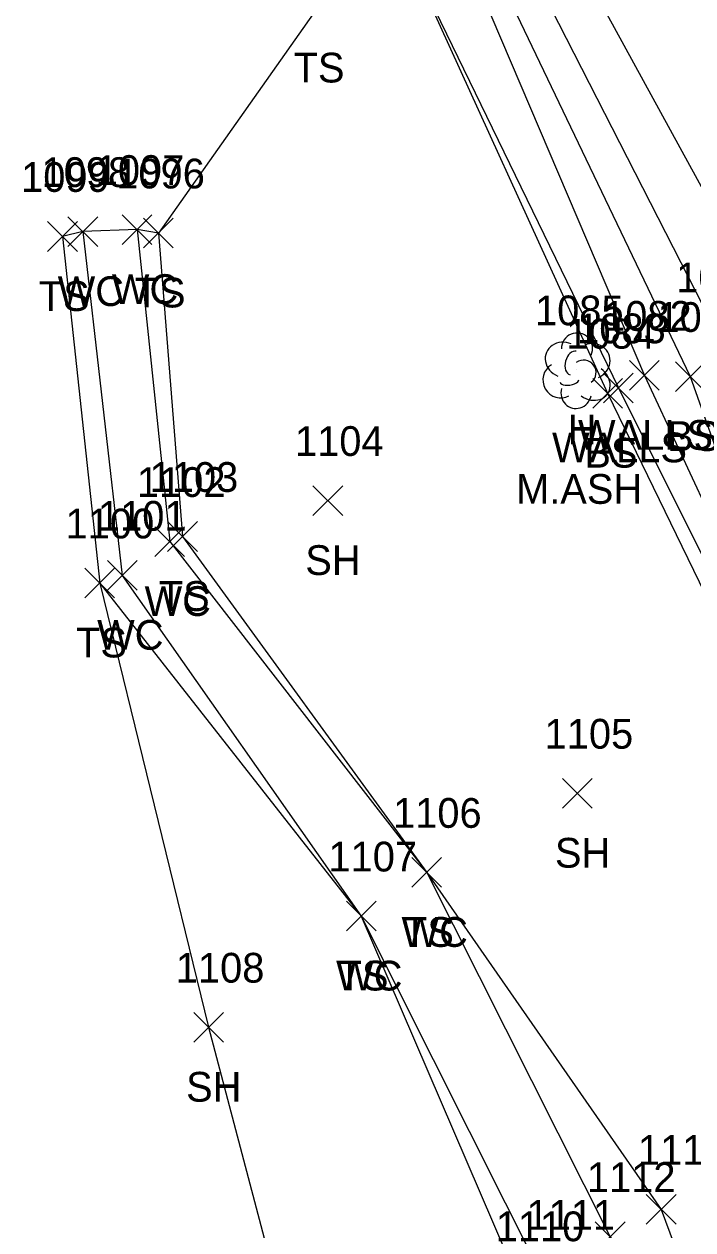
# Model space of a CAD drawing. Extents: x 1441651 to 1442140, y 243798 to 245625.
# Drawn here: x 1441903.8 to 1441948.7, y 245501.1 to 245582.1 of the extents above; entities that cross this region are included whole.
import ezdxf

# ---------------------------------------------------------------- set-up
doc = ezdxf.new("R2010")
doc.units = 0
for name, color, linetype in [('L_A', 7, 'Continuous'), ('L_C', 7, 'Continuous'), ('L_I', 7, 'Continuous'), ('L_TIC', 7, 'Continuous'), ('LAWE', 7, 'Continuous'), ('LELB', 7, 'Continuous'), ('LSOGP', 7, 'Continuous'), ('LTD', 7, 'Continuous'), ('LWS', 7, 'Continuous'), ('PEU', 7, 'Continuous')]:
    doc.layers.add(name, color=color, linetype=linetype)

msp = doc.modelspace()

# ---------------------------------------------------------------- linework, layer by layer
at = {"layer": 'L_TIC'}
for points in [[(1441905.336, 245566.87), (1441907.336, 245568.87)], [(1441907.336, 245566.87), (1441905.336, 245568.87)], [(1441906.704, 245567.198), (1441908.704, 245569.198)], [(1441908.704, 245567.198), (1441906.704, 245569.198)], [(1441910.342, 245567.336), (1441912.342, 245569.336)], [(1441912.342, 245567.336), (1441910.342, 245569.336)], [(1441911.774, 245567.104), (1441913.774, 245569.104)], [(1441913.774, 245567.104), (1441911.774, 245569.104)], [(1441944.41, 245557.535), (1441946.41, 245559.535)], [(1441946.41, 245557.535), (1441944.41, 245559.535)], [(1441947.491, 245557.459), (1441949.491, 245559.459)], [(1441949.491, 245557.459), (1441947.491, 245559.459)], [(1441941.939, 245556.338), (1441943.939, 245558.338)], [(1441943.939, 245556.338), (1441941.939, 245558.338)], [(1441942.666, 245556.696), (1441944.666, 245558.696)], [(1441944.666, 245556.696), (1441942.666, 245558.696)], [(1441923.153, 245549.123), (1441925.153, 245551.123)], [(1441925.153, 245549.123), (1441923.153, 245551.123)], [(1441912.54, 245546.368), (1441914.54, 245548.368)], [(1441914.54, 245546.368), (1441912.54, 245548.368)], [(1441913.394, 245546.708), (1441915.394, 245548.708)], [(1441915.394, 245546.708), (1441913.394, 245548.708)], [(1441909.354, 245544.097), (1441911.354, 245546.097)], [(1441911.354, 245544.097), (1441909.354, 245546.097)], [(1441907.838, 245543.581), (1441909.838, 245545.581)], [(1441909.838, 245543.581), (1441907.838, 245545.581)], [(1441939.916, 245529.451), (1441941.916, 245531.451)], [(1441941.916, 245529.451), (1441939.916, 245531.451)], [(1441929.794, 245524.129), (1441931.794, 245526.129)], [(1441931.794, 245524.129), (1441929.794, 245526.129)], [(1441929.794, 245524.129), (1441931.794, 245526.129)], [(1441931.794, 245524.129), (1441929.794, 245526.129)], [(1441925.401, 245521.195), (1441927.401, 245523.195)], [(1441927.401, 245521.195), (1441925.401, 245523.195)], [(1441925.401, 245521.195), (1441927.401, 245523.195)], [(1441927.401, 245521.195), (1441925.401, 245523.195)], [(1441915.149, 245513.724), (1441917.149, 245515.724)], [(1441917.149, 245513.724), (1441915.149, 245515.724)], [(1441945.539, 245501.48), (1441947.539, 245503.48)], [(1441947.539, 245501.48), (1441945.539, 245503.48)], [(1441942.112, 245499.641), (1441944.112, 245501.641)], [(1441944.112, 245499.641), (1441942.112, 245501.641)]]:
    msp.add_lwpolyline(points, dxfattribs=at)
at = {"layer": 'LAWE'}
for points in [[(1441907.704, 245568.198), (1441910.354, 245545.097), (1441926.401, 245522.195), (1441938.487, 245498.109), (1441943.431, 245489.962), (1441943.382, 245477.871), (1441945.819, 245463.28), (1441949.518, 245451.716), (1441958.04, 245451.396), (1441967.21, 245432.067), (1441993.811, 245408.343), (1442003.996, 245402.527), (1442022.028, 245379.959)], [(1441911.342, 245568.336), (1441913.54, 245547.368), (1441930.794, 245525.129), (1441943.112, 245500.641), (1441948.928, 245491.303), (1441946.177, 245479.068), (1441949.055, 245463.199), (1441952.693, 245455.284), (1441960.253, 245454.331), (1441970.926, 245435.223), (1441995.301, 245411.435), (1442005.916, 245405.86), (1442024.361, 245389.769), (1442032.995, 245390.022)]]:
    msp.add_lwpolyline(points, dxfattribs=at)
at = {"layer": 'LELB'}
for points in [[(1441935.553, 245590.253), (1441950.412, 245561.12), (1441965.846, 245535.511), (1441982.294, 245505.635), (1441993.222, 245488.677)], [(1441933.718, 245589.334), (1441948.491, 245558.459), (1441956.206, 245536.697), (1441975.054, 245500.102), (1441979.331, 245493.092), (1441987.533, 245478.538), (1441986.565, 245474.385), (1441981.273, 245469.984), (1441969.099, 245476.162)], [(1441929.024, 245587.875), (1441942.939, 245557.338), (1441953.315, 245535.956), (1441954.957, 245536.46), (1441956.206, 245536.697)], [(1441923.447, 245583.224), (1441912.774, 245568.104), (1441914.394, 245547.708), (1441930.794, 245525.129), (1441946.539, 245502.48), (1441950.678, 245491.319), (1441947.348, 245479.457), (1441950.826, 245463.211), (1441954.445, 245457.195), (1441962.212, 245455.423), (1441972.577, 245437.756), (1441995.951, 245413.456), (1442007.462, 245408.084), (1442021.352, 245397.079), (1442029.302, 245403.168), (1442035.632, 245410.326), (1442039.926, 245412.912), (1442042.785, 245414.272)], [(1441906.336, 245567.87), (1441908.838, 245544.581), (1441926.401, 245522.195), (1441937.072, 245497.343), (1441939.983, 245490.583), (1441942.033, 245477.517), (1441944.373, 245463.316), (1441948.224, 245450.684), (1441957.161, 245448.976), (1441965.891, 245430.984), (1441993.118, 245407.16), (1442003.121, 245400.589), (1442010.091, 245391.874)]]:
    msp.add_lwpolyline(points, dxfattribs=at)
at = {"layer": 'LSOGP'}
msp.add_lwpolyline([(1441923.447, 245583.224), (1441912.774, 245568.104), (1441911.342, 245568.336), (1441907.704, 245568.198), (1441906.336, 245567.87), (1441908.838, 245544.581), (1441916.149, 245514.724), (1441923.283, 245487.648)], dxfattribs=at)
at = {"layer": 'LTD'}
msp.add_line((1441940.839, 245558.905), (1441940.839, 245558.905), dxfattribs=at)
msp.add_line((1441940.839, 245558.905), (1441940.839, 245558.905), dxfattribs=at)
msp.add_arc((1441940.886, 245560.339), 1.047, 335.52715, 180.95627, dxfattribs=at)
for centre, major_axis, ratio, start_param, end_param in [((1441940.047, 245559.572), (1.21, -0.512), 0.895232, 1.570796, 4.712389), ((1441941.881, 245559.489), (-1.141, -0.483), 0.949671, 1.570796, 4.712389), ((1441940.631, 245559.364), (-0.208, -0.792), 0.645439, 3.141593, 6.283185), ((1441939.756, 245558.197), (0.584, -1.042), 0.959034, 3.141593, 6.283185), ((1441941.339, 245558.739), (-0.5, 0.667), 0.989748, 3.141593, 6.283185), ((1441941.839, 245558.072), (-1.09, 0.792), 0.841452, 1.570796, 4.712389), ((1441940.381, 245558.155), (-0.625, -0.083), 0.423636, 0, 3.141593), ((1441940.839, 245557.405), (0.265, 1.061), 0.942809, 1.570796, 4.712389)]:
    msp.add_ellipse(centre, major_axis=major_axis, ratio=ratio, start_param=start_param, end_param=end_param, dxfattribs=at)
at = {"layer": 'LWS'}
for points in [[(1441932.574, 245588.698), (1441945.41, 245558.535), (1441955.19, 245537.551)], [(1441929.024, 245587.875), (1441943.666, 245557.696), (1441954.048, 245536.929), (1441955.19, 245537.551)]]:
    msp.add_lwpolyline(points, dxfattribs=at)
at = {"layer": 'PEU'}
msp.add_lwpolyline([(1441937.939, 245591.884), (1441953.89, 245562.719), (1441968.906, 245535.694), (1441984.797, 245506.977), (1441992.987, 245492.297), (1442013.076, 245458.975), (1442024.733, 245444.52), (1442043.134, 245414.629), (1442048.272, 245419.302), (1442053.641, 245424.38)], dxfattribs=at)

# ---------------------------------------------------------------- texts
at = {"layer": 'L_A'}
for s, p in [('TS', (1441921.856, 245578.224)), ('WC', (1441909.649, 245563.336)), ('TS', (1441904.746, 245562.87)), ('WC', (1441906.011, 245563.198)), ('TS', (1441911.183, 245563.104)), ('H', (1441940.272, 245553.905)), ('WALLS', (1441940.953, 245553.535)), ('BS', (1441946.932, 245553.459)), ('WALLS', (1441939.209, 245552.696)), ('BS', (1441941.38, 245552.338)), ('SH', (1441922.642, 245545.123)), ('WC', (1441911.847, 245542.368)), ('TS', (1441912.803, 245542.708)), ('WC', (1441908.661, 245540.097)), ('TS', (1441907.247, 245539.581)), ('SH', (1441939.404, 245525.451)), ('WC', (1441929.101, 245520.129)), ('TS', (1441929.203, 245520.129)), ('WC', (1441924.708, 245517.195)), ('TS', (1441924.81, 245517.195)), ('SH', (1441914.637, 245509.724))]:
    msp.add_text(s, height=2, dxfattribs=at).set_placement(p)
at = {"layer": 'L_C'}
msp.add_text('M.ASH', height=2, dxfattribs=at).set_placement((1441936.792, 245549.905))
at = {"layer": 'L_I'}
for s, p in [('1099', (1441903.557, 245570.87)), ('1098', (1441904.932, 245571.198)), ('1097', (1441908.57, 245571.336)), ('1096', (1441909.947, 245571.104)), ('1080', (1441947.553, 245564.12)), ('1085', (1441938.067, 245561.905)), ('1082', (1441942.638, 245561.535)), ('1081', (1441946.286, 245561.459)), ('1084', (1441940.167, 245560.338)), ('1083', (1441940.894, 245560.696)), ('1104', (1441921.949, 245553.123)), ('1102', (1441911.335, 245550.368)), ('1103', (1441912.189, 245550.708)), ('1101', (1441908.716, 245548.097)), ('1100', (1441906.546, 245547.581)), ('1105', (1441938.712, 245533.451)), ('1106', (1441928.534, 245528.129)), ('1106', (1441928.534, 245528.129)), ('1107', (1441924.196, 245525.195)), ('1107', (1441924.196, 245525.195)), ('1108', (1441913.944, 245517.724)), ('1113', (1441944.98, 245505.48)), ('1112', (1441941.553, 245503.641)), ('1111', (1441937.495, 245501.109)), ('1110', (1441935.427, 245500.343))]:
    msp.add_text(s, height=2, dxfattribs=at).set_placement(p)

doc.saveas('drawing.dxf')
